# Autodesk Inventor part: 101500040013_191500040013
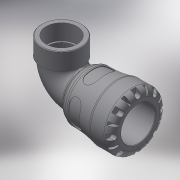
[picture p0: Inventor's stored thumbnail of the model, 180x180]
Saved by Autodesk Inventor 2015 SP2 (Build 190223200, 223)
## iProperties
Created: 2016-12
Part Number: 101500040013_191500040013
Material: Generic
Description: PLASSON 90° ELBOW WITH THREADED FEMALE OFFTAKE 40X1.1/4" SERIES 1
Document SubType Name: Modeling
Designer: KIM
Mass: 557.611 g
Surface Area: 990.043 cm^2
Volume: 557.611 cm^3
Density: 1 g/cm^3
Appearance: Default
Author: KIM
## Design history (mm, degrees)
derived "1015.ipt"
feature "Solid1::1015.ipt"
tag "TaggingFeature1"
body "Solid1"
other parameters: "d1" = 30.24, "d8" = 61.6, "d13" = 8, "d14" = 8, "d15" = 0, "d17" = 360 deg, "d19" = 8 deg, "d20" = 0.8, "d21" = 0.8, "d22" = 8 deg, "d24" = 0, "d26" = 360 deg, "d33" = 7, "d43" = 57.4, "d51" = 0.7, "d54" = 14, "d55" = 8.8, "d57" = 15.68, "d58" = 0, "d74" = 0, "d78" = 72, "d82" = 0.8, "d115" = 360 deg, "d207" = 90 deg, "d228" = 11.9, "d247" = 1.4, "d248" = 4.32, "d268" = 33.88, "d269" = 4.32, "d270" = 107, "d279" = 61, "d281" = 5.8428, "d294" = 38.952, "d295" = 24, "d296" = 26.4, "d297" = 35.0568, "d299" = 45.57384, "d300" = 35.0568, "d301" = 0, "d302" = 0, "d303" = 5.91308, "d306" = 0, "d307" = 9, "d308" = 8, "d310" = 3, "l_" = 72, "A_" = 107, "A_1" = 61, "l_2" = 24, "Rp_" = 38.952, "d298" = 50.6376
